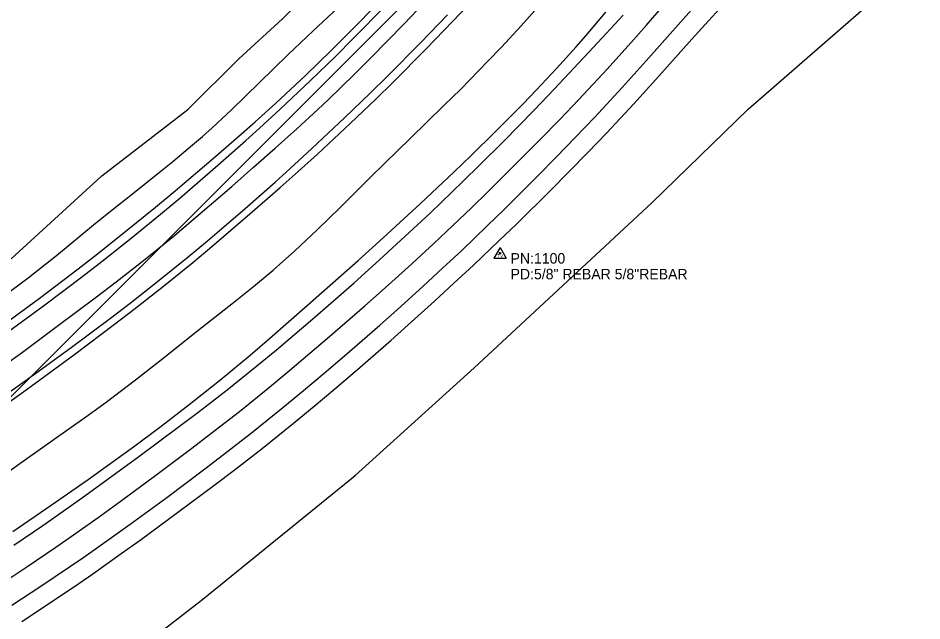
# Model space of a CAD drawing. Extents: x 1676038 to 1677961, y 226475 to 233854.
# Drawn here: x 1676776.5 to 1677206.8, y 227687.2 to 227974.2 of the extents above; entities that cross this region are included whole.
import ezdxf

# ---------------------------------------------------------------- set-up
doc = ezdxf.new("R2010")
doc.units = 0
for name, color, linetype in [('S_BASELINE', 7, 'Continuous'), ('S_DITCHLINE', 7, 'Continuous'), ('S_EDGE_PAVEMENT', 7, 'Continuous'), ('S_FIBER_OPTIC_CABLE', 7, 'Continuous'), ('S_PAVEMENT_CROWN', 7, 'Continuous'), ('S_SECONDARY_CTL', 7, 'Continuous'), ('S_SECONDARY_CTL_ANNOT', 7, 'Continuous'), ('S_SHOULDER', 7, 'Continuous'), ('S_UTL_PT_SYM', 7, 'Continuous')]:
    doc.layers.add(name, color=color, linetype=linetype)

msp = doc.modelspace()

# ---------------------------------------------------------------- linework, layer by layer
at = {"layer": 'S_BASELINE'}
msp.add_line((1676625.89, 227646.73), (1677368.16, 228389.18), dxfattribs=at)
at = {"layer": 'S_DITCHLINE'}
for points in [[(1676768.81, 227841.12), (1676781.31, 227850.55), (1676794.72, 227861.22), (1676812.4, 227875.73), (1676821.28, 227882.95), (1676830.91, 227890.62), (1676843.77, 227900.81), (1676850.15, 227905.95), (1676859.6, 227913.82), (1676864.24, 227917.84), (1676868.89, 227922.01), (1676878.02, 227930.53), (1676891.46, 227943.62), (1676904.91, 227956.71), (1676917.04, 227968.18), (1676933.22, 227983.46)], [(1676765.94, 227753.99), (1676779.59, 227763.79), (1676792.57, 227772.92), (1676809.85, 227785.11), (1676818.4, 227791.33), (1676832.36, 227801.97), (1676846.14, 227812.86), (1676859.92, 227823.76), (1676879.09, 227838.84), (1676888.6, 227846.47), (1676897.95, 227854.27), (1676902.55, 227858.26), (1676908.13, 227863.25), (1676919.05, 227873.5), (1676929.77, 227883.98), (1676943.92, 227898.11), (1676951.02, 227905.16), (1676963.08, 227916.92), (1676979.21, 227932.56), (1676987.2, 227940.45), (1677000.17, 227953.65), (1677006.55, 227960.36), (1677015.99, 227970.55), (1677025.23, 227980.9)]]:
    msp.add_lwpolyline(points, dxfattribs=at)
at = {"layer": 'S_EDGE_PAVEMENT'}
for points in [[(1676772.03, 227825.14), (1676788.62, 227837.24), (1676807.31, 227851.32), (1676816.56, 227858.49), (1676830.31, 227869.4), (1676844.24, 227880.82), (1676853.44, 227888.54), (1676871.63, 227904.22), (1676884.89, 227915.95), (1676891.46, 227921.87), (1676901.25, 227930.84), (1676915.74, 227944.48), (1676927.9, 227956.29), (1676935.92, 227964.26), (1676951.76, 227980.38)], [(1676773.52, 227694.75), (1676787.29, 227703.77), (1676800.96, 227712.96), (1676807.74, 227717.62), (1676821.02, 227726.94), (1676829.81, 227733.24), (1676847.27, 227746), (1676865.35, 227759.54), (1676874.33, 227766.39), (1676887.68, 227776.81), (1676902.58, 227788.79), (1676912.41, 227796.9), (1676922.15, 227805.14), (1676931.88, 227813.37), (1676948.66, 227827.99), (1676956.98, 227835.38), (1676969.35, 227846.58), (1676978.52, 227855.1), (1676987.68, 227863.63), (1676999.83, 227875.26), (1677007.86, 227883.09), (1677023.76, 227898.92), (1677032.82, 227908.22), (1677041.88, 227917.51), (1677050.82, 227926.92), (1677064.06, 227941.19), (1677075.56, 227953.94), (1677090.78, 227971.04), (1677098.41, 227979.59)], [(1676763.8, 227790.32), (1676776.54, 227799.18), (1676784.98, 227805.17), (1676801.74, 227817.32), (1676820.56, 227831.36), (1676829.88, 227838.49), (1676843.73, 227849.37), (1676857.53, 227860.58), (1676866.63, 227868.17), (1676884.63, 227883.6), (1676898.83, 227896.15), (1676905.87, 227902.49), (1676916.35, 227912.09), (1676931.88, 227926.7), (1676944.11, 227938.52), (1676952.18, 227946.48), (1676968.16, 227962.57), (1676980.99, 227975.79)], [(1676774.51, 227723.28), (1676788.32, 227732.7), (1676795.19, 227737.48), (1676808.2, 227746.7), (1676821.09, 227756.09), (1676833.98, 227765.47), (1676852.77, 227779.44), (1676862.1, 227786.51), (1676875.97, 227797.27), (1676890.15, 227808.64), (1676899.5, 227816.34), (1676917.98, 227832.01), (1676936.44, 227848.2), (1676948.6, 227859.15), (1676956.64, 227866.52), (1676972.6, 227881.4), (1676988.37, 227896.5), (1676996.17, 227904.12), (1677007.75, 227915.68), (1677022.13, 227930.45), (1677031.62, 227940.39), (1677041.04, 227950.41), (1677050.47, 227960.42), (1677064.47, 227975.57)]]:
    msp.add_lwpolyline(points, dxfattribs=at)
at = {"layer": 'S_FIBER_OPTIC_CABLE'}
for p, q in [((1676902.41, 227973.8), (1676941.57, 228013.45)), ((1677124.03, 227930.86), (1677206.22, 228002.56)), ((1676881.55, 227954.79), (1676902.41, 227973.8)), ((1676857.28, 227930.62), (1676881.55, 227954.79)), ((1676816.44, 227899.08), (1676857.28, 227930.62)), ((1677078.18, 227886.24), (1677124.03, 227930.86)), ((1676773.26, 227859.62), (1676816.44, 227899.08)), ((1676993.59, 227807.69), (1677078.18, 227886.24)), ((1676936.92, 227756.51), (1676993.59, 227807.69)), ((1676864.37, 227697.61), (1676936.92, 227756.51)), ((1676821.12, 227663.91), (1676864.37, 227697.61))]:
    msp.add_line(p, q, dxfattribs=at)
at = {"layer": 'S_PAVEMENT_CROWN'}
for points in [[(1676766.67, 227703.83), (1676780.65, 227712.98), (1676794.49, 227722.33), (1676801.36, 227727.08), (1676814.6, 227736.48), (1676823.36, 227742.84), (1676840.79, 227755.69), (1676859.15, 227769.42), (1676868.28, 227776.36), (1676881.84, 227786.93), (1676896.36, 227798.66), (1676905.93, 227806.61), (1676924.9, 227822.74), (1676941.58, 227837.25), (1676949.86, 227844.57), (1676962.19, 227855.65), (1676974.4, 227866.87), (1676980.44, 227872.54), (1676992.37, 227883.95), (1677000.25, 227891.63), (1677015.87, 227907.15), (1677025.12, 227916.55), (1677034.37, 227925.96), (1677043.5, 227935.48), (1677056.99, 227949.95), (1677068.17, 227962.37), (1677075.53, 227970.74), (1677090.09, 227987.61)], [(1676770.18, 227809.13), (1676778.53, 227815.24), (1676795.14, 227827.6), (1676813.86, 227841.57), (1676823.17, 227848.63), (1676836.98, 227859.39), (1676850.91, 227870.74), (1676860.08, 227878.46), (1676878.25, 227894.1), (1676888.59, 227903.18), (1676898.92, 227912.26), (1676909.14, 227921.46), (1676919.24, 227930.77), (1676924.24, 227935.49), (1676936.46, 227947.31), (1676944.49, 227955.3), (1676960.36, 227971.5), (1676969.86, 227981.46)]]:
    msp.add_lwpolyline(points, dxfattribs=at)
at = {"layer": 'S_SECONDARY_CTL'}
for p, q in [((1677005.94, 227864.94), (1677002.93, 227859.99)), ((1677005.94, 227864.94), (1677008.89, 227859.99)), ((1677002.93, 227859.99), (1677008.89, 227859.99))]:
    msp.add_line(p, q, dxfattribs=at)
for radius in [0.311, 0.183, 0.103]:
    msp.add_circle((1677005.94, 227862.33), radius, dxfattribs=at)
at = {"layer": 'S_SHOULDER'}
for points in [[(1676769.95, 227828.57), (1676786.46, 227840.75), (1676805.03, 227854.85), (1676814.23, 227862), (1676827.93, 227872.86), (1676841.95, 227884.27), (1676851.23, 227891.96), (1676869.6, 227907.56), (1676882.78, 227919.03), (1676889.32, 227924.83), (1676899.05, 227933.62), (1676913.43, 227947.02), (1676925.55, 227958.78), (1676933.54, 227966.71), (1676949.36, 227982.73)], [(1676778.26, 227686.98), (1676791.9, 227695.91), (1676805.42, 227705.02), (1676812.13, 227709.66), (1676825.64, 227719.24), (1676834.58, 227725.72), (1676852.37, 227738.82), (1676870.37, 227752.23), (1676879.32, 227759.01), (1676892.63, 227769.3), (1676907.6, 227781.29), (1676917.46, 227789.41), (1676927.22, 227797.68), (1676936.97, 227805.94), (1676953.88, 227820.66), (1676962.26, 227828.1), (1676974.74, 227839.37), (1676983.99, 227847.94), (1676993.24, 227856.51), (1677005.57, 227868.27), (1677013.73, 227876.18), (1677029.88, 227892.15), (1677038.8, 227901.22), (1677047.73, 227910.29), (1677056.53, 227919.47), (1677069.55, 227933.42), (1677081.45, 227946.55), (1677097.2, 227964.17), (1677105.11, 227972.94), (1677117.45, 227986.37)], [(1676765.93, 227787.04), (1676778.55, 227795.98), (1676786.9, 227802.03), (1676803.5, 227814.28), (1676822.41, 227828.48), (1676831.8, 227835.67), (1676845.75, 227846.62), (1676859.62, 227857.9), (1676868.77, 227865.53), (1676886.9, 227881.02), (1676901.24, 227893.54), (1676908.36, 227899.86), (1676918.96, 227909.41), (1676934.66, 227923.98), (1676946.86, 227935.69), (1676954.9, 227943.6), (1676970.81, 227959.61), (1676983.65, 227972.85), (1676990.02, 227979.53)], [(1676773.96, 227729.76), (1676792.33, 227742.34), (1676809.79, 227754.55), (1676818.46, 227760.73), (1676831.39, 227770.12), (1676843.92, 227779.42), (1676850.14, 227784.14), (1676859.4, 227791.3), (1676873.12, 227802.25), (1676887.01, 227813.8), (1676896.16, 227821.63), (1676914.3, 227837.49), (1676926.31, 227848.15), (1676938.32, 227858.82), (1676950.25, 227869.58), (1676967.99, 227885.88), (1676984.05, 227901.03), (1676992, 227908.68), (1677003.82, 227920.28), (1677016.89, 227933.41), (1677023.33, 227940.06), (1677032.86, 227950.17), (1677042.18, 227960.47), (1677046.75, 227965.69), (1677056.34, 227977.09)]]:
    msp.add_lwpolyline(points, dxfattribs=at)
at = {"layer": 'S_UTL_PT_SYM'}
for points in [[(1676902.41, 227973.8), (1676902.41, 227973.85), (1676902.41, 227973.8), (1676902.36, 227973.8), (1676902.41, 227973.8), (1676902.41, 227973.75), (1676902.41, 227973.8), (1676902.46, 227973.8)], [(1676881.55, 227954.79), (1676881.55, 227954.84), (1676881.55, 227954.79), (1676881.5, 227954.79), (1676881.55, 227954.79), (1676881.55, 227954.74), (1676881.55, 227954.79), (1676881.6, 227954.79)], [(1677124.03, 227930.86), (1677124.03, 227930.91), (1677124.03, 227930.86), (1677123.98, 227930.86), (1677124.03, 227930.86), (1677124.03, 227930.81), (1677124.03, 227930.86), (1677124.08, 227930.86)], [(1676857.28, 227930.62), (1676857.28, 227930.67), (1676857.28, 227930.62), (1676857.23, 227930.62), (1676857.28, 227930.62), (1676857.28, 227930.57), (1676857.28, 227930.62), (1676857.33, 227930.62)], [(1676816.44, 227899.08), (1676816.44, 227899.13), (1676816.44, 227899.08), (1676816.39, 227899.08), (1676816.44, 227899.08), (1676816.44, 227899.03), (1676816.44, 227899.08), (1676816.49, 227899.08)], [(1677078.18, 227886.24), (1677078.18, 227886.29), (1677078.18, 227886.24), (1677078.13, 227886.24), (1677078.18, 227886.24), (1677078.18, 227886.19), (1677078.18, 227886.24), (1677078.23, 227886.24)], [(1676993.59, 227807.69), (1676993.59, 227807.74), (1676993.59, 227807.69), (1676993.54, 227807.69), (1676993.59, 227807.69), (1676993.59, 227807.64), (1676993.59, 227807.69), (1676993.64, 227807.69)], [(1676936.92, 227756.51), (1676936.92, 227756.56), (1676936.92, 227756.51), (1676936.87, 227756.51), (1676936.92, 227756.51), (1676936.92, 227756.46), (1676936.92, 227756.51), (1676936.97, 227756.51)], [(1676864.37, 227697.61), (1676864.37, 227697.66), (1676864.37, 227697.61), (1676864.32, 227697.61), (1676864.37, 227697.61), (1676864.37, 227697.56), (1676864.37, 227697.61), (1676864.42, 227697.61)]]:
    msp.add_lwpolyline(points, dxfattribs=at)

# ---------------------------------------------------------------- texts
at = {"layer": 'S_SECONDARY_CTL'}
msp.add_text('TV', height=1.5, rotation=360, dxfattribs=at).set_placement((1677004.74, 227860.32))
at = {"layer": 'S_SECONDARY_CTL_ANNOT'}
for s, p in [('PN:1100', (1677010.94, 227857.33)), ('PD:5/8" REBAR 5/8"REBAR', (1677010.94, 227849.83))]:
    msp.add_text(s, height=5, dxfattribs=at).set_placement(p)

doc.saveas('drawing.dxf')
